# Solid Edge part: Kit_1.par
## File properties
Sűrűség: 0,000 kg/m^3
Pontosság: 0,990
Author: ahadarics
Last saved by: psaghy
Revision: 78
Username: ahadarics
Dokumentum tartalom típus: 0
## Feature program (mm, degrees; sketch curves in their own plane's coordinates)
base feature "unnamed BaseFeature 1"
sketch for "Furat_6" plane through (0, 0, 50) normal (0, 0, 1) x-axis (1, 0, 0)
  hole centre (-87.5, 87.5) bore radius 6.9175
hole "Furat_6" nominal diameter 16 finite  ThreadDepth = 24 mm
sketch for "unnamed Hole 1" plane through (0, 0, 50) normal (0, 0, 1) x-axis (1, 0, 0)
  hole centre (-87.5, -87.5) bore radius 6.9175
hole "unnamed Hole 1" finite
sketch for "unnamed Hole 2" plane through (0, 0, 50) normal (0, 0, 1) x-axis (1, 0, 0)
  hole centre (87.5, -87.5) bore radius 6.9175
hole "unnamed Hole 2" finite
sketch for "unnamed Hole 3" plane through (0, 0, 50) normal (0, 0, 1) x-axis (1, 0, 0)
  hole centre (87.5, 87.5) bore radius 6.9175
hole "unnamed Hole 3" finite
pattern "unnamed Pattern 1" of "Furat_6", "unnamed Hole 1", "unnamed Hole 2", "unnamed Hole 3"
sketch for "Furat_10" plane through (15, -109, 24.5) normal (0, -1, 0) x-axis (0, 0, -1)
hole "Furat_10" diameter 26.441 finite  ThreadDepth = 27 mm
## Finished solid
Body 1: solid body, 611 faces, 1445 edges, 884 vertices, 3 internal voids.
  Faces by surface: cylinder 196, plane 173, torus 99, cone 54, spline 54, swept 24, sphere 11
  Edges by curve: line 504, curve on surface 447, circle 424, spline 51, intersection 16, ellipse 3
Bounding box of the edges (mm; curved faces can reach further): 220.000 x 220.000 x 115.000, from (-110, -110, 0) to (110, 110, 115).
Cylindrical faces by radius (mm): R0.4595 x1, R0.4687 x2, R0.5232 x1, R0.5393 x1, R0.5479 x1, R0.5619 x1, R0.5738 x1, R0.6109 x1, R0.6383 x1, R0.6502 x1, R0.6941 x1, R0.8155 x1, R0.8225 x2, R0.8412 x1, R0.8677 x1, R0.8728 x1, R0.9072 x1, R0.9543 x1, R0.9562 x1, R1 x19, R1.0017 x2, R1.0187 x1, R1.0708 x1, R1.1067 x1, R1.3671 x1, R1.5 x4, R1.5039 x1, R1.5591 x1, R1.5808 x1, R1.6101 x1, R1.6481 x1, R1.7807 x1, R1.8842 x1, R1.9083 x1, R2 x41, R2.2009 x1, R2.6379 x1, R2.75 x1, R3 x33, R4 x1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
Conical faces (half-angle, radius in mm at the cone's reference point): 0.0011 deg R3.025 x12, 1.6538 deg R21.75 x1, 3.5477 deg R22.7454 x1, 5.1705 deg R20.4 x1, 8.3742 deg R20.0032 x1, 13.2989 deg R21.1846 x1, 14.7738 deg R20.7787 x1, 25.0169 deg R24.31 x1, 30 deg R22.3557 x2, 30 deg R22.7887 x1, 45 deg R3.85 x1, 45 deg R4.25 x1, 45 deg R6.9 x12, 45 deg R8.9 x8, 45 deg R12.055 x1, 45 deg R13.5 x4, 45 deg R20.5 x4, 45 deg R25.35 x1
Toroidal faces (ring radius, tube radius in mm): R1 r2 x3, R3.0044 r1.0018 x12, R3.0124 r1.0019 x8, R4 r1 x8, R4 r2 x2, R5.85 r0.2 x1, R6.0853 r3.0032 x6, R6.0855 r3.0034 x6, R12 r0.5 x12, R14 r2 x1, R16 r2 x1, R17 r1 x1, R18 r1 x4, R20 r2 x1, R20.3088 r0.3 x1, R20.5 r1.5 x4, R21 r2 x4, R21.4279 r0.25 x1, R22 r3 x8, R22.2464 r0.5 x1, R24.8 r0.2 x1, R33.5 r1.5 x1, R35.5 r2 x1, R36 r1 x1, R38 r2 x1, R38.5 r1 x1, R42 r2 x8
Spherical faces by radius (mm): R2 x3, R3 x8
Planar faces by outward normal: +x 12, +y 7, +z 55, -x 11, -y 28, -z 14, oblique 46
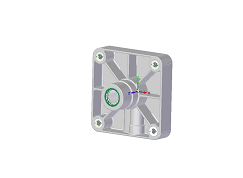
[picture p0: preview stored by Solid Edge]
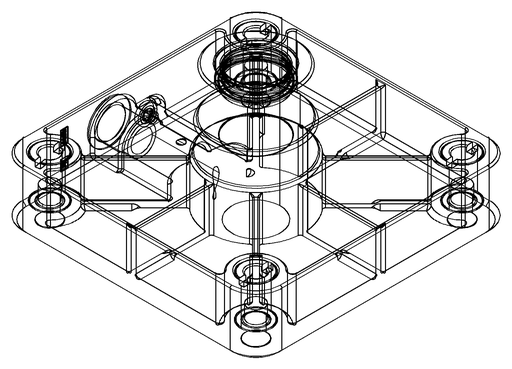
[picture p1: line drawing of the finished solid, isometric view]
